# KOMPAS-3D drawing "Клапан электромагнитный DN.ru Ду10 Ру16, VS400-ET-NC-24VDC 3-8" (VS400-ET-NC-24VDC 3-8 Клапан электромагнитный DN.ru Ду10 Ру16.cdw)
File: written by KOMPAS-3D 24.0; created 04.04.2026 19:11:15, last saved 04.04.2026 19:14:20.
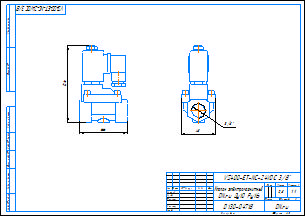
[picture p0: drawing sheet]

Document properties: c3d_UniqueCompID: ef56311e-7521-43dc-8291-0e6108b3d81d; Обозначение: VS400-ET-NC-220VAC 3-8; Наименование: Клапан электромагнитный DN.ru Ду10 Ру16; Автор: artio; Класс точности: c; Знак неуказанной шероховатости: Шероховатость не задана; Рассекать на разрезах: Да; Автор: artio; Форматы листов документа: A3; Полное имя файла: VS400-ET-NC-24VDC 3-8 Клапан электромагнитный DN.ru Ду10 Ру16.m3d; Масса: 0.797; Наименование: Клапан электромагнитный DN.ru Ду10 Ру16; Количество листов документа: 1; Примечание: D130-04718

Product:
- Body: Тело 1  | qty 1
    Масса: 1.030062
- Part/product: Клапан электромагнитный DN.ru Ду10 Ру16  | designation VS400-ET-NC-24VDC 3-8
    Масса: 0.797
    Раздел спецификации: Прочие изделия
    Форматы листов документа: A3
    Примечание: D130-04718
    additional columns: ef56311e-7521-43dc-8291-0e6108b3d81d; VS400-ET-NC-220VAC 3-8; artio; c; Шероховатость не задана; Да

Views: Вид 1, Спереди, Проекционный вид 2
Referenced files in C:\Users\artio\OneDrive\Рабочий стол\Клапан электромагнитный DN.ru\VS400-ET-NC\VS400-ET-NC-24VDC\: VS400-ET-NC-24VDC 3-8 Клапан электромагнитный DN.ru Ду10 Ру16.m3d
Referenced files in C:\Users\artio\OneDrive\Рабочий стол\Клапан электромагнитный DN.ru\VS400\VS400-ET-NC\VS400-ET-NC-24VDC\Ду10\: VS400-ET-NC-24VDC 3-8 Клапан электромагнитный DN.ru Ду10 Ру16.cdw, VS400-ET-NC-24VDC 3-8 Клапан электромагнитный DN.ru Ду10 Ру16.m3d
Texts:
  VS400-ET-NC-24VDC 3-8
  Клапан электромагнитный
  DN.ru Ду10 Ру16
  VS400-ET-NC-24VDC 3/8"
  VS400-ET-NC-24VDC 3/8"-
  Клапан электромагнитный DN.ru Ду10 Ру16
  VS400-ET-NC-24VDC 3-8 Клапан электромагнитный DN.ru Ду10 Ру16
Dimensions and other numbers on the sheet: 0; 3; 2; 4; 48; 3/8"; 66; 106; 1:1; 1; 0,8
